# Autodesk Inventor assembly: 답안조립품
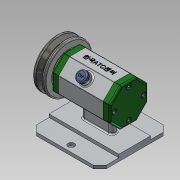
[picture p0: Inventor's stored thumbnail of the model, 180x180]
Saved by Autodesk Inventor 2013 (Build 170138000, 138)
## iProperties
Created: 2018-06
Part Number: 답안조립품
Document SubType Name: Assembly
Designer: default
Author: default
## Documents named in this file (16)
- C:\Users\default.default-PC\Desktop\480608V1003\답안조립품.iam
- C:\Users\default.default-PC\Desktop\480608V1003\본체.ipt
- C:\Users\default.default-PC\Desktop\480608V1003\베어링 15x32x9.ipt
- C:\Users\default.default-PC\Desktop\480608V1003\뒤커버.ipt
- C:\Users\default.default-PC\Desktop\480608V1003\앞커버.ipt
- C:\Users\default.default-PC\Desktop\480608V1003\오일 실 15 25 7.ipt
- C:\Users\default.default-PC\Desktop\480608V1003\볼트 M4x12.ipt
- C:\Users\default.default-PC\Desktop\480608V1003\축.ipt
- C:\Users\default.default-PC\Desktop\480608V1003\키 3x3x12.ipt
- 키 3x3x12.ipt
- C:\Users\default.default-PC\Desktop\480608V1003\V벨트풀리.ipt
- C:\Users\default.default-PC\Desktop\480608V1003\와셔 8x17.ipt
- C:\Users\default.default-PC\Desktop\480608V1003\스프링와셔 8.ipt
- C:\Users\default.default-PC\Desktop\480608V1003\너트 M8.ipt
- 너트 M8.ipt
- C:\Users\default.default-PC\Desktop\480608V1003\고무캡.ipt
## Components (2 placed, 2 different names)
1. V벨트풀리:1 — 각도:1
2. 고무캡:1
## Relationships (1: Angle 1)
- 각도:1 [Angle]: V벨트풀리:1
